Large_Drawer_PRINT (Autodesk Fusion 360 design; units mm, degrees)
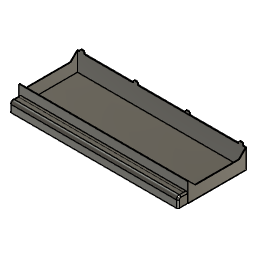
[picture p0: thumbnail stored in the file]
sketch "Sketch1" plane through (0, 0, 0) normal (0, 0, 1) x axis (1, 0, 0)
  line L1 (229.4, 0) -> (0, 0)
  line L2 (229.4, 80) -> (229.4, 0)
  line L3 (0, 80) -> (229.4, 80)
  line L4 (0, 0) -> (0, 80)
  point P1 (0, 0)
  point P2 (0, 0)
  point P3 (229.4, 0)
  point P4 (229.4, 80)
  horizontal L1
  vertical L2
  horizontal L3
  vertical L4
  coincident P1 P2
  dimension "d1" distance P2 P3 = 229.4 (= "230.2 mm - 0.8 mm")
  dimension "d2" distance P3 P4 = 80
extrude "Extrude1" new body sketch "Sketch1" along normal blind 26.2
shell "Shell1" innerThickness 0.8
work_plane "WorkPlane1" AlongDistance -18.4
sketch "Sketch3" plane through (0, 80, 0) normal (0, 1, 0) x axis (-1, 0, 0)
  line L1 (0, 0) -> (-229.4, 0)
  line L2 (0, 26.2) -> (0, 0)
  line L3 (-229.4, 26.2) -> (0, 26.2)
  line L4 (-229.4, 0) -> (-229.4, 26.2)
  line L5 (-114.7, 0) -> (-114.7, 26.2)
  line L6 (-225.15, 28.45) -> (-225.15, 27.45)
  line L7 (-220.9, 29.7) -> (-223.9, 29.7)
  line L8 (-219.65, 27.45) -> (-219.65, 28.45)
  line L9 (-218.4, 26.2) -> (-226.4, 26.2)
  line L10 (-8.5, 29.7) -> (-5.5, 29.7)
  line L11 (-4.25, 28.45) -> (-4.25, 27.45)
  line L12 (-11, 26.2) -> (-3, 26.2)
  line L13 (-9.75, 27.45) -> (-9.75, 28.45)
  line L14 (-148.4, 29.7129) -> (-151.4, 29.7129)
  line L15 (-152.65, 28.4629) -> (-152.65, 27.4629)
  line L16 (-145.9, 26.2129) -> (-153.9, 26.2129)
  line L17 (-147.15, 27.4629) -> (-147.15, 28.4629)
  line L18 (-78, 29.7) -> (-81, 29.7)
  line L19 (-82.25, 28.45) -> (-82.25, 27.45)
  line L20 (-76.75, 27.45) -> (-76.75, 28.45)
  arc A1 centre (-226.4, 27.45) radius 1.25 clockwise from (-225.15, 27.45) to (-226.4, 26.2)
  arc A2 centre (-223.9, 28.45) radius 1.25 clockwise from (-225.15, 28.45) to (-223.9, 29.7)
  arc A3 centre (-220.9, 28.45) radius 1.25 clockwise from (-220.9, 29.7) to (-219.65, 28.45)
  arc A4 centre (-218.4, 27.45) radius 1.25 clockwise from (-218.4, 26.2) to (-219.65, 27.45)
  arc A5 centre (-5.5, 28.45) radius 1.25 clockwise from (-5.5, 29.7) to (-4.25, 28.45)
  arc A6 centre (-11, 27.45) radius 1.25 clockwise from (-9.75, 27.45) to (-11, 26.2)
  arc A7 centre (-3, 27.45) radius 1.25 clockwise from (-3, 26.2) to (-4.25, 27.45)
  arc A8 centre (-8.5, 28.45) radius 1.25 clockwise from (-9.75, 28.45) to (-8.5, 29.7)
  arc A9 centre (-151.4, 28.4629) radius 1.25 clockwise from (-152.65, 28.4629) to (-151.4, 29.7129)
  arc A10 centre (-153.9, 27.4629) radius 1.25 clockwise from (-152.65, 27.4629) to (-153.9, 26.2129)
  arc A11 centre (-145.9, 27.4629) radius 1.25 clockwise from (-145.9, 26.2129) to (-147.15, 27.4629)
  arc A12 centre (-148.4, 28.4629) radius 1.25 clockwise from (-148.4, 29.7129) to (-147.15, 28.4629)
  arc A13 centre (-81, 28.45) radius 1.25 clockwise from (-82.25, 28.45) to (-81, 29.7)
  arc A14 centre (-83.5, 27.45) radius 1.25 clockwise from (-82.25, 27.45) to (-83.5, 26.2)
  arc A15 centre (-78, 28.45) radius 1.25 clockwise from (-78, 29.7) to (-76.75, 28.45)
  arc A16 centre (-75.5, 27.45) radius 1.25 clockwise from (-75.5, 26.2) to (-76.75, 27.45)
  point P10 (-114.7, 26.2)
  point P11 (-114.7, 0)
  point P20 (-222.4, 29.7)
  point P12 (-225.15, 27.45)
  point P27 (-4.25, 27.45)
  point P13 (-225.15, 28.45)
  point P21 (-4.25, 28.45)
  point P14 (-223.9, 29.7)
  point P28 (-5.5, 29.7)
  point P15 (-220.9, 29.7)
  point P26 (-8.5, 29.7)
  point P16 (-219.65, 28.45)
  point P23 (-9.75, 28.45)
  point P17 (-219.65, 27.45)
  point P22 (-9.75, 27.45)
  point P18 (-226.4, 26.2)
  point P30 (-3, 26.2)
  point P19 (-218.4, 26.2)
  point P29 (-11, 26.2)
  point P31 (-7, 29.7)
  midpoint L3 P10
  perpendicular L3 L5
  coincident L1 P11
  horizontal L7
  tangent L7 A2
  tangent L6 A2
  tangent L6 A1
  tangent L7 A3
  tangent L8 A3
  tangent L8 A4
  tangent L9 A4
  tangent L9 A1
  equal A1 A2
  equal A2 A3
  equal A3 A4
  collinear L3 L9
  vertical L8
  vertical L6
  midpoint L7 P20
  symmetric L5 P12 P27
  symmetric L5 P13 P21
  symmetric L5 P14 P28
  symmetric L5 P15 P26
  symmetric L5 P16 P23
  symmetric L5 P17 P22
  symmetric L5 P18 P30
  symmetric L5 P19 P29
  symmetric L5 P20 P31
  symmetric L5 A1 A7
  symmetric L5 A2 A5
  symmetric L5 A3 A8
  symmetric L5 A4 A6
  horizontal L14
  tangent L14 A9
  tangent A9 L15
  tangent L15 A10
  tangent L14 A12
  tangent L17 A12
  tangent A11 L17
  tangent A11 L16
  tangent A10 L16
  equal A9 A10
  equal A9 A12
  equal A11 A12
  vertical L17
  vertical L15
  horizontal L18
  tangent L18 A13
  tangent A13 L19
  tangent L19 A14
  tangent L18 A15
  tangent A15 L20
  tangent L20 A16
  equal A13 A14
  equal A13 A15
  equal A15 A16
  vertical L20
  vertical L19
  dimension "d18" distance L4 P20 = 7
  dimension "d19" distance L7 L9 = 3.5
  dimension "d20" distance L6 L8 = 5.5
  dimension "d21" radius A1 = 1.25
  dimension "d62" distance L14 L16 = 3.5
  dimension "d63" distance L15 L17 = 5.5
  dimension "d64" radius A10 = 1.25
  dimension "d65" = 114.3
  dimension "d66" distance L8 L15 = 67
  dimension "d75" distance L19 L20 = 5.5
  dimension "d76" radius A14 = 1.25
  dimension "d77" distance L3 L18 = 3.5
  dimension "d78" distance L13 L20 = 67
  dimension "d79" = 54.15
extrude "Extrude3" add sketch "Sketch3" profile of L3 A1 A2 A3 A4 L6 L7 L8 L9 A5 L10 A6 A7 L11 L12 A8 L13 L14 A9 L15 A10 A11 L16 L17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 against normal blind 0.8
sketch "Sketch4" plane through (229.4, 0, 0) normal (1, 0, 0) x axis (0, 1, 0)
  line L1 (80, 0) -> (0, 0)
  line L2 (80, 26.2) -> (80, 0)
  line L3 (0, 26.2) -> (80, 26.2)
  line L4 (0, 0) -> (0, 26.2)
  line L5 (10.1071, 17) -> (0.9071, 26.2)
  line L6 (7.8528, 26.2) -> (0.9071, 26.2)
  line L7 (69.7311, 17) -> (10.1071, 17)
  line L8 (78.9311, 26.2) -> (69.7311, 17)
  line L9 (0.9071, 26.2) -> (78.9311, 26.2)
  point P6 (0.9071, 26.2)
  point P10 (78.9311, 26.2)
  horizontal L6
  coincident L3 P6
  horizontal L7
  coincident L3 P10
  dimension "d24" angle L5 L6 = 45
  dimension "d25" angle L7 L8 = 135
  dimension "d26" distance L1 L7 = 17
extrude "Extrude4" cut sketch "Sketch4" profile of L3 L5 L7 L8 L9 to an object
extrude "Extrude5" add of existing geometry blind 0.4
sketch "Sketch5" plane through (0, 0, 0) normal (0, -1, 0) x axis (1, 0, 0)
  line L1 (229.4, 0) -> (0, 0)
  line L2 (229.4, 26.2) -> (229.4, 0)
  line L3 (0, 26.2) -> (229.4, 26.2)
  line L4 (0, 0) -> (0, 26.2)
  line L5 (228.9, 13.8) -> (0.5, 13.8)
  line L6 (228.9, 13) -> (228.9, 13.8)
  line L7 (0.5, 13) -> (228.9, 13)
  line L8 (0.5, 13.8) -> (0.5, 13)
  horizontal L5
  vertical L6
  horizontal L7
  vertical L8
  dimension "d31" distance L4 L8 = 0.5
  dimension "d32" distance L2 L6 = 0.5
  dimension "d33" distance L5 L7 = 0.8
  dimension "d34" distance L1 L7 = 13
extrude "Extrude6" add sketch "Sketch5" profile of L5 L6 L7 L8 along normal blind 13
sketch "Sketch6" plane through (0, 0, 13) normal (0, 0, -1) x axis (1, 0, 0)
  line L1 (228.9, 0) -> (0.5, 0)
  line L2 (228.9, 13) -> (228.9, 0)
  line L3 (0.5, 13) -> (228.9, 13)
  line L4 (0.5, 0) -> (0.5, 13)
  line L5 (31.3, 13) -> (0.5, 13)
  line L6 (0.5, 12.2) -> (31.3, 12.2)
  line L7 (0.5, 13) -> (0.5, 12.2)
  line L8 (228.9, 13) -> (31.3, 13)
  line L9 (228.9, 12.2) -> (31.3, 12.2)
  line L10 (228.9, 13) -> (228.9, 12.2)
  point P5 (0.5, 13)
  point P6 (0.5, 13)
  point P4 (228.9, 13)
  point P10 (228.9, 13)
  point P11 (228.9, 12.2)
  point P9 (0.5, 12.2)
  horizontal L5
  horizontal L6
  vertical L7
  coincident P5 P6
  coincident P4 P10
  coincident L2 P11
  perpendicular L2 L9
  dimension "d37" distance P6 P9 = 0.8
extrude "Extrude7" add sketch "Sketch6" profile of L2 L3 L4 L5 L6 L7 L8 L9 L10 along normal blind 13
sketch "Sketch8" plane through (0, 0, 13) normal (0, 0, -1) x axis (1, 0, 0)
  line L1 (0.5, 12.2) -> (228.9, 12.2)
  line L2 (0.5, 0) -> (0.5, 12.2)
  line L3 (228.9, 0) -> (0.5, 0)
  line L4 (228.9, 12.2) -> (228.9, 0)
  line L5 (0.5, 0) -> (1.3, 0)
  line L6 (0.5, 12.2) -> (0.5, 0)
  line L7 (1.3, 12.2) -> (0.5, 12.2)
  line L8 (1.3, 0) -> (1.3, 12.2)
  line L9 (228.1, 0) -> (228.9, 0)
  line L10 (228.1, 12.2) -> (228.1, 0)
  line L11 (228.9, 12.2) -> (228.1, 12.2)
  line L12 (228.9, 0) -> (228.9, 12.2)
  point P3 (0.5, 12.2)
  point P8 (0.5, 12.2)
  point P6 (1.3, 0)
  point P12 (228.1, 12.2)
  point P5 (228.9, 0)
  point P10 (228.9, 0)
  point P13 (228.9, 12.2)
  point P9 (1.3, 12.2)
  horizontal L5
  vertical L6
  horizontal L7
  vertical L8
  coincident P3 P8
  coincident L3 P6
  horizontal L9
  vertical L10
  horizontal L11
  vertical L12
  coincident L1 P12
  coincident P5 P10
  dimension "d45" distance P12 P13 = 0.8
  dimension "d46" distance P8 P9 = 0.8
extrude "Extrude9" add sketch "Sketch8" along normal blind 13
fillet "Fillet2" radius 4
chamfer "Chamfer1" distance 3
fillet "Fillet4" radius 2
fillet "Fillet5" radius 2
fillet "Fillet6" radius 2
